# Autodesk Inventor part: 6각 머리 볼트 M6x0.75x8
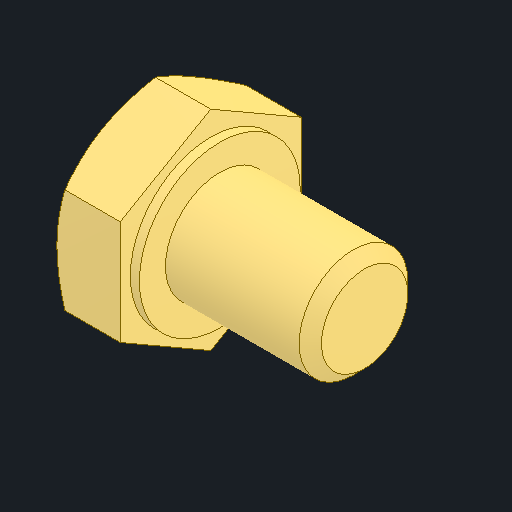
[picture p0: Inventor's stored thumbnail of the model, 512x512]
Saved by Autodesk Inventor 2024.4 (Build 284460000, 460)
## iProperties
Created: 2025-10
Part Number: 6각 머리 볼트 M6x0.75x8
Material: 강철, 연강
Description: 6각 머리 볼트 및 6각 머리 나사
Document SubType Name: Modeling
Designer: user
Density: 7.85 g/cm^3
Appearance: 기본값
Author: jhkim
Sending System: Autodesk Inventor 2026
Preprocessor: ST-DEVELOPER v20.1
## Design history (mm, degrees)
feature "Solid1"
node "솔리드1"
